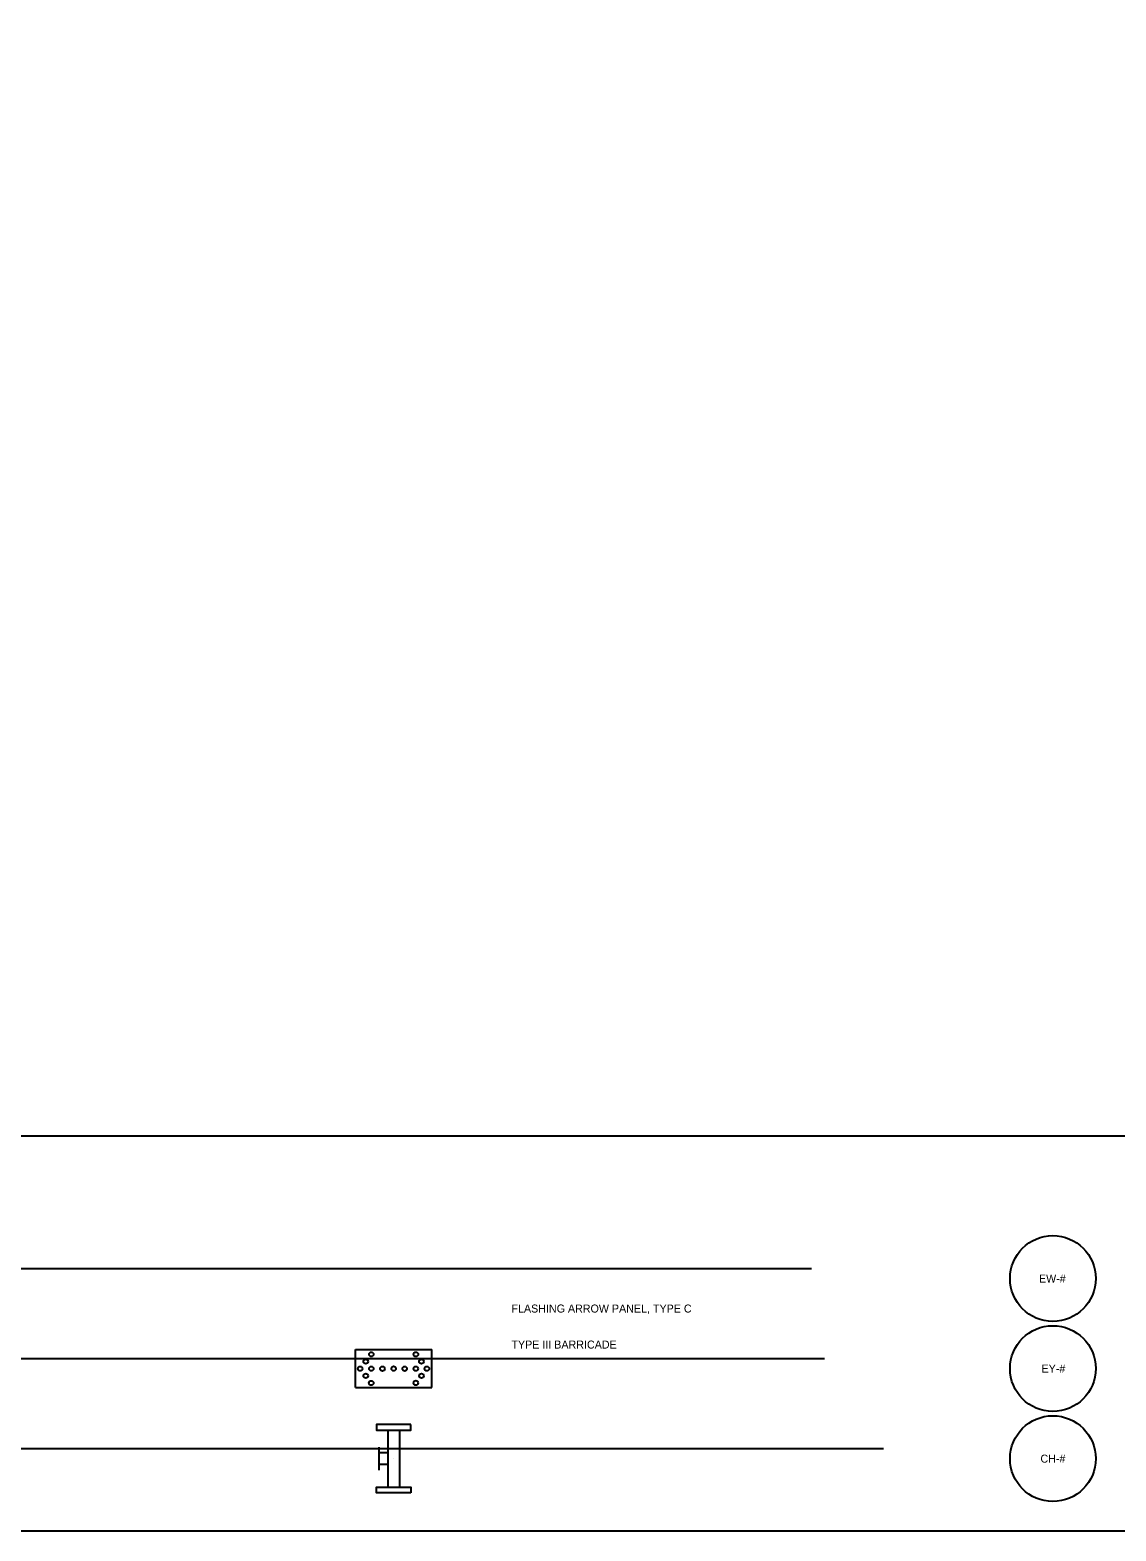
# Model space of a CAD drawing. Extents: x 75 to 1600, y 25 to 1075.
# Drawn here: x 455 to 835, y 25 to 550 of the extents above; entities that cross this region are included whole.
import ezdxf

# ---------------------------------------------------------------- set-up
doc = ezdxf.new("R2010")
doc.units = 0
for name, color, linetype in [('Default', 7, 'Continuous'), ('SC_Scratch1', 7, 'Continuous'), ('SC_Scratch2', 7, 'Continuous'), ('SH_Text', 7, 'Continuous')]:
    doc.layers.add(name, color=color, linetype=linetype)

msp = doc.modelspace()

# ---------------------------------------------------------------- linework, layer by layer
at = {"layer": 'Default'}
for p, q in [((568.95, 88.46), (595.62, 88.46)), ((568.95, 75.13), (568.95, 88.46)), ((595.62, 75.13), (595.62, 88.46)), ((568.95, 75.13), (595.62, 75.13)), ((580.28, 60.3), (580.28, 40.3)), ((584.28, 60.3), (584.28, 40.3)), ((577.28, 46.3), (577.28, 54.3)), ((580.28, 52.3), (577.28, 52.3)), ((580.28, 48.3), (577.28, 48.3)), ((582.28, 50.3), (582.28, 50.3))]:
    msp.add_line(p, q, dxfattribs=at)
for points in [[(588.28, 62.3), (576.28, 62.3), (576.28, 60.3), (588.28, 60.3)], [(588.28, 38.3), (576.28, 38.3), (576.28, 40.3), (588.28, 40.3)]]:
    msp.add_lwpolyline(points, close=True, dxfattribs=at)
for centre in [(572.53, 84.28), (574.49, 86.79), (590.08, 86.79), (592.01, 84.29), (570.59, 81.77), (572.53, 79.26), (574.47, 81.78), (578.36, 81.74), (582.28, 81.8), (586.16, 81.75), (590.07, 81.78), (592.02, 79.27), (593.93, 81.77), (574.46, 76.75), (590.07, 76.78)]:
    msp.add_circle(centre, 0.799, dxfattribs=at)
at = {"layer": 'SC_Scratch1'}
for points in [[(75, 25), (1600, 25), (1600, 1075), (75, 1075)], [(75, 25), (1600, 25), (1600, 163.11), (75, 163.11)]]:
    msp.add_lwpolyline(points, close=True, dxfattribs=at)
at = {"layer": 'SC_Scratch2'}
for p, q in [((150.32, 116.8), (728.57, 116.8)), ((150.32, 85.3), (733.02, 85.3)), ((150.32, 53.8), (753.76, 53.8))]:
    msp.add_line(p, q, dxfattribs=at)
at = {"layer": 'SH_Text'}
for centre in [(812.99, 113.3), (812.99, 81.8), (812.99, 50.3)]:
    msp.add_circle(centre, 15, dxfattribs=at)

# ---------------------------------------------------------------- texts
for s, p in [('EW-#', (808.12, 111.9)), ('FLASHING ARROW PANEL, TYPE C', (623.52, 101.4)), ('TYPE III BARRICADE', (623.52, 88.8)), ('EY-#', (809.01, 80.4)), ('CH-#', (808.64, 48.9))]:
    msp.add_text(s, height=2.8, dxfattribs=at).set_placement(p)

doc.saveas('drawing.dxf')
